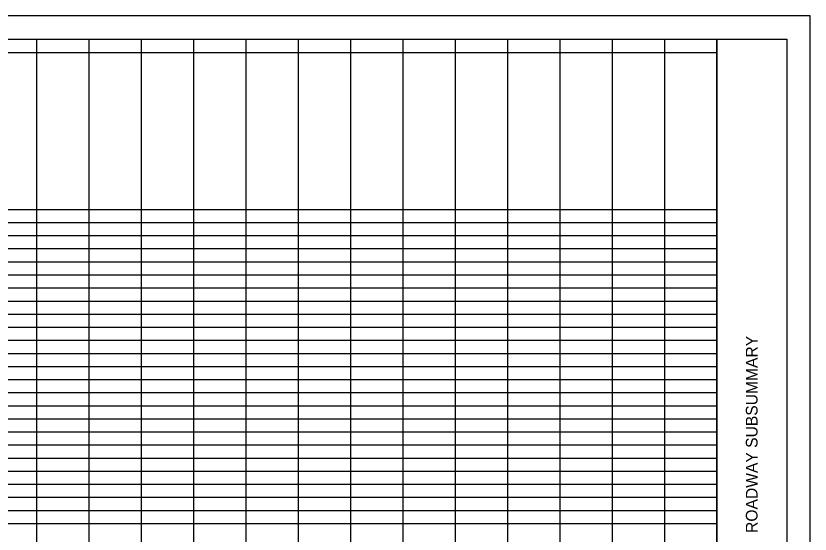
# Model space of a CAD drawing. Extents: x 0 to 34, y 0 to 22.
# Drawn here: x 17 to 34, y 10.91 to 22 of the extents above; entities that cross this region are included whole.
import ezdxf

# ---------------------------------------------------------------- set-up
doc = ezdxf.new("R2010")
doc.units = 0
for name, color, linetype in [('SH_Border', 7, 'Continuous'), ('SH_Cut_Line', 7, 'Continuous'), ('SH_Data', 7, 'Continuous'), ('SH_Text', 7, 'Continuous')]:
    doc.layers.add(name, color=color, linetype=linetype)

msp = doc.modelspace()

# ---------------------------------------------------------------- linework, layer by layer
at = {"layer": 'SH_Border'}
msp.add_line((32, 0.5), (32, 21.5), dxfattribs=at)
msp.add_lwpolyline([(1.5, 21.5), (33.5, 21.5), (33.5, 0.5), (1.5, 0.5)], close=True, dxfattribs=at)
at = {"layer": 'SH_Cut_Line'}
msp.add_lwpolyline([(0, 0), (34, 0), (34, 22), (0, 22)], close=True, dxfattribs=at)
at = {"layer": 'SH_Text'}
for p, q in [((1.5, 21.5), (32.002, 21.5)), ((17.443, 21.5), (17.443, 0.501)), ((18.563, 21.5), (18.563, 0.501)), ((19.683, 21.5), (19.683, 0.501)), ((20.803, 21.5), (20.803, 0.501)), ((21.923, 21.5), (21.923, 0.501)), ((23.043, 21.5), (23.043, 0.501)), ((24.163, 21.5), (24.163, 0.501)), ((25.283, 21.5), (25.283, 0.501)), ((26.403, 21.5), (26.403, 0.501)), ((27.523, 21.5), (27.523, 0.501)), ((28.643, 21.5), (28.643, 0.501)), ((29.763, 21.5), (29.763, 0.501)), ((30.882, 21.5), (30.882, 0.501)), ((32.002, 21.5), (32.002, 0.501)), ((8.483, 21.22), (32.002, 21.22)), ((8.483, 17.86), (32.002, 17.86)), ((1.5, 17.58), (32.002, 17.58)), ((1.5, 17.3), (32.002, 17.3)), ((1.5, 17.02), (32.002, 17.02)), ((1.5, 16.74), (32.002, 16.74)), ((1.5, 16.46), (32.002, 16.46)), ((1.5, 16.18), (32.002, 16.18)), ((1.5, 15.9), (32.002, 15.9)), ((1.5, 15.62), (32.002, 15.62)), ((1.5, 15.34), (32.002, 15.34)), ((1.5, 15.06), (32.002, 15.06)), ((1.5, 14.78), (32.002, 14.78)), ((1.5, 14.5), (32.002, 14.5)), ((1.5, 14.22), (32.002, 14.22)), ((1.5, 13.94), (32.002, 13.94)), ((1.5, 13.66), (32.002, 13.66)), ((1.5, 13.38), (32.002, 13.38)), ((1.5, 13.1), (32.002, 13.1)), ((1.5, 12.82), (32.002, 12.82)), ((1.5, 12.54), (32.002, 12.54)), ((1.5, 12.26), (32.002, 12.26)), ((1.5, 11.98), (32.002, 11.98)), ((1.5, 11.7), (32.002, 11.7)), ((1.5, 11.42), (32.002, 11.42)), ((1.5, 11.14), (32.002, 11.14))]:
    msp.add_line(p, q, dxfattribs=at)

# ---------------------------------------------------------------- texts
at = {"layer": 'SH_Data'}
msp.add_text('ROADWAY SUBSUMMARY', height=0.25, rotation=90, dxfattribs=at).set_placement((32.875, 10.938))

doc.saveas('drawing.dxf')
